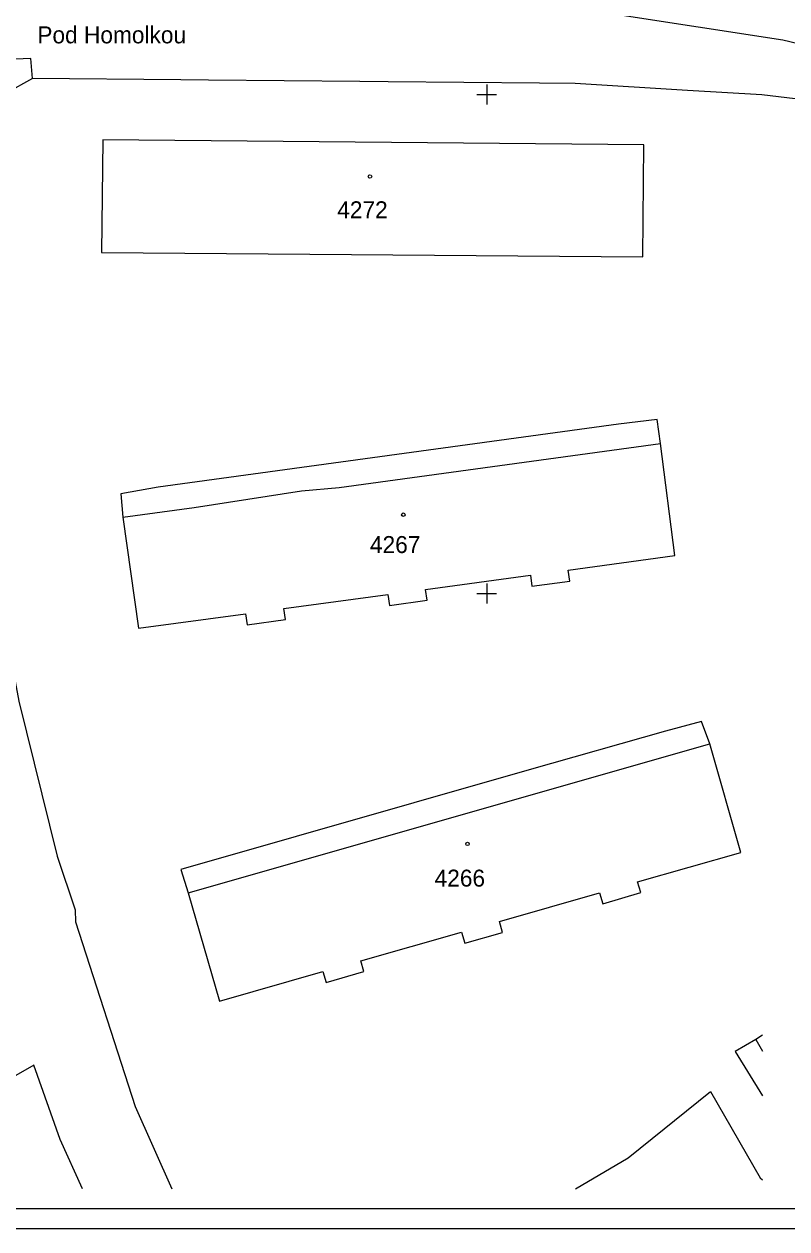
# Model space of a CAD drawing. Extents: x -771260 to -770828, y -1053564 to -1052811.
# Drawn here: x -770996.4 to -770919.9, y -1053563.7 to -1053442.9 of the extents above; entities that cross this region are included whole.
import ezdxf

# ---------------------------------------------------------------- set-up
doc = ezdxf.new("R2010")
doc.units = 0
for name, color, linetype in [('14_8_2023_krizky', 7, 'Continuous'), ('25_3_2019_krizky_JTSK', 7, 'Continuous'), ('25_3_2019_ram_ggs', 7, 'Continuous'), ('DKM_Hranice parcel', 7, 'Continuous'), ('DKM_Parcelní čísla', 7, 'Continuous'), ('DKM_Pop  PČ popisy', 7, 'Continuous'), ('DKM_Vnitřní kresba', 7, 'Continuous'), ('DKM_Značky budov', 7, 'Continuous')]:
    doc.layers.add(name, color=color, linetype=linetype)

# ---------------------------------------------------------------- blocks, each defined once
blk = doc.blocks.new('KRIZEK')
at = {"layer": '25_3_2019_krizky_JTSK'}
for p, q in [((-10, 0), (10, 0)), ((0, 10), (0, -10))]:
    blk.add_line(p, q, dxfattribs=at)

msp = doc.modelspace()

# ---------------------------------------------------------------- linework, layer by layer
at = {"layer": '25_3_2019_ram_ggs'}
for points in [[(-771251.02, -1053563.67), (-771251.02, -1052969.17), (-770830.52, -1052969.17), (-770830.52, -1053563.67)], [(-771249.02, -1053561.67), (-771249.02, -1052971.17), (-770832.52, -1052971.17), (-770832.52, -1053561.67)]]:
    msp.add_lwpolyline(points, close=True, dxfattribs=at)
at = {"layer": 'DKM_Hranice parcel'}
for points in [[(-770945.78, -1053440.6), (-770920.32, -1053444.5), (-770910.7, -1053446.8), (-770854.69, -1053456.35)], [(-770995.53, -1053448.4), (-770995.7, -1053446.37), (-771019.76, -1053447.41)], [(-770995.53, -1053448.4), (-771000.85, -1053451.31), (-771002.68, -1053456.47), (-771001.71, -1053471.17), (-771000.38, -1053488.14), (-770999.83, -1053495.25), (-770996.88, -1053510.77), (-770993.04, -1053526.32), (-770991.25, -1053531.68), (-770991.21, -1053532.9), (-770985.24, -1053551.41), (-770981.55, -1053559.67)], [(-770901.63, -1053452.84), (-770906.3, -1053451.96), (-770922.42, -1053450.01), (-770929.87, -1053449.57), (-770941.12, -1053448.88), (-770944.71, -1053448.85), (-770959.89, -1053448.71), (-770962.72, -1053448.68), (-770977.88, -1053448.55), (-770980.67, -1053448.52), (-770995.53, -1053448.4)], [(-770934.35, -1053466.27), (-770934.25, -1053455.02), (-770988.46, -1053454.52), (-770988.59, -1053465.83), (-770934.35, -1053466.27)], [(-770974.17, -1053502.03), (-770974.01, -1053503.15), (-770970.18, -1053502.61), (-770970.33, -1053501.51), (-770959.9, -1053500.09), (-770959.75, -1053501.21), (-770955.98, -1053500.65), (-770956.12, -1053499.58), (-770945.62, -1053498.16), (-770945.47, -1053499.27), (-770941.68, -1053498.77), (-770941.83, -1053497.64), (-770931.13, -1053496.19), (-770932.58, -1053484.97), (-770932.91, -1053482.56), (-770936.79, -1053483.02), (-770982.93, -1053489.33), (-770986.67, -1053490.01), (-770986.46, -1053492.34), (-770984.9, -1053503.48), (-770974.17, -1053502.03)], [(-770928.47, -1053512.82), (-770932.07, -1053513.78), (-770945.75, -1053517.68), (-770980.66, -1053527.65), (-770979.93, -1053529.98), (-770976.77, -1053540.84), (-770966.41, -1053537.89), (-770966.1, -1053538.98), (-770962.31, -1053537.89), (-770962.61, -1053536.81), (-770952.51, -1053533.93), (-770952.19, -1053535.04), (-770948.41, -1053533.97), (-770948.73, -1053532.85), (-770938.68, -1053529.99), (-770938.36, -1053531.1), (-770934.56, -1053529.96), (-770934.87, -1053528.9), (-770924.52, -1053525.95), (-770927.64, -1053515.06), (-770928.47, -1053512.82)], [(-770922.34, -1053544.26), (-770923.04, -1053544.68), (-770925.11, -1053545.9), (-770922.34, -1053550.35)], [(-770990.52, -1053559.67), (-770992.75, -1053554.72), (-770995.4, -1053547.25), (-770997.2, -1053548.3)], [(-770941.11, -1053559.67), (-770935.82, -1053556.55), (-770927.56, -1053549.9), (-770922.58, -1053558.56), (-770922.34, -1053558.75)]]:
    msp.add_lwpolyline(points, dxfattribs=at)
at = {"layer": 'DKM_Vnitřní kresba'}
for p, q in [((-770964.78, -1053489.38), (-770932.58, -1053484.97)), ((-770979.31, -1053491.37), (-770968.55, -1053489.7)), ((-770968.55, -1053489.7), (-770964.78, -1053489.38)), ((-770986.46, -1053492.34), (-770979.31, -1053491.37)), ((-770979.93, -1053529.98), (-770927.64, -1053515.06)), ((-770923.04, -1053544.68), (-770922.34, -1053545.86))]:
    msp.add_line(p, q, dxfattribs=at)
at = {"layer": 'DKM_Značky budov'}
for centre in [(-770961.7, -1053458.21), (-770958.36, -1053492.1), (-770951.92, -1053525.09)]:
    msp.add_circle(centre, 0.175, dxfattribs=at)

# ---------------------------------------------------------------- block references
at = {"layer": '14_8_2023_krizky', "xscale": 0.1, "yscale": 0.10000000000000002}
for p in [(-770950, -1053450), (-770950, -1053500)]:
    msp.add_blockref('KRIZEK', p, dxfattribs=at)

# ---------------------------------------------------------------- texts
at = {"layer": 'DKM_Parcelní čísla'}
for s, p in [('4272', (-770964.98, -1053462.39)), ('4267', (-770961.7, -1053495.94)), ('4266', (-770955.22, -1053529.37))]:
    msp.add_text(s, height=1.7, dxfattribs=at).set_placement(p)
at = {"layer": 'DKM_Pop  PČ popisy'}
msp.add_text('Pod Homolkou', height=1.7, dxfattribs=at).set_placement((-770995.04, -1053444.86))

doc.saveas('drawing.dxf')
